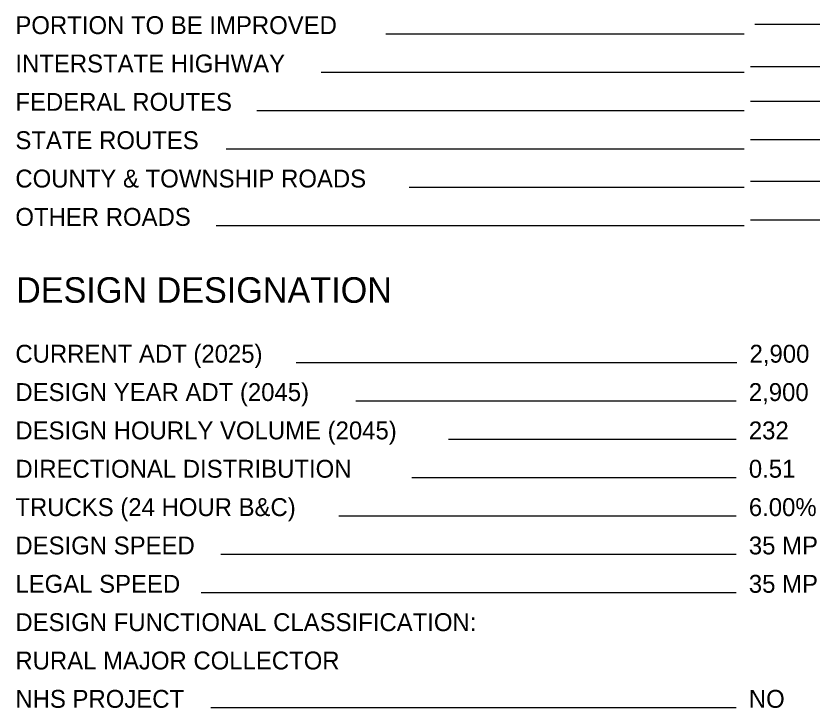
# Model space of a CAD drawing. Extents: x -13.9 to 69.1, y -25.2 to 26.1.
# Drawn here: x 1.73 to 7.96, y -18.58 to -13.17 of the extents above; entities that cross this region are included whole.
import ezdxf

# ---------------------------------------------------------------- set-up
doc = ezdxf.new("R2010")
doc.units = 0
doc.layers.add('SH_Data', color=7, linetype='Continuous')
doc.layers.add('SH_Text', color=7, linetype='Continuous')

msp = doc.modelspace()

# ---------------------------------------------------------------- linework, layer by layer
at = {"layer": 'SH_Data'}
for p, q in [((7.5134, -13.2313), (8.7308, -13.2313)), ((7.4308, -13.31), (4.6245, -13.31)), ((8.7308, -13.5659), (7.4808, -13.5659)), ((7.4308, -13.61), (4.1203, -13.61)), ((8.7308, -13.8376), (7.4808, -13.8376)), ((7.4308, -13.91), (3.6162, -13.91)), ((8.7308, -14.1376), (7.4808, -14.1376)), ((7.4308, -14.21), (3.3755, -14.21)), ((7.4308, -14.51), (4.8089, -14.51)), ((8.7308, -14.4643), (7.4808, -14.4643)), ((8.7308, -14.7643), (7.4808, -14.7643)), ((7.4308, -14.81), (3.2965, -14.81)), ((7.3732, -15.8804), (3.9244, -15.8804)), ((7.3676, -16.1804), (4.39, -16.1804)), ((7.3676, -16.4804), (5.116, -16.4804)), ((7.3676, -16.7804), (4.8295, -16.7804)), ((7.3676, -17.0804), (4.2566, -17.0804)), ((7.3676, -17.3804), (3.3343, -17.3804)), ((7.3676, -17.6804), (3.1796, -17.6804)), ((7.3676, -18.5804), (3.255, -18.5804))]:
    msp.add_line(p, q, dxfattribs=at)

# ---------------------------------------------------------------- texts
msp.add_text('DESIGN DESIGNATION', height=0.2, dxfattribs=at).set_placement((1.7308, -15.412))
at = {"layer": 'SH_Text'}
for s, p in [('PORTION TO BE IMPROVED', (1.7252, -13.31)), ('INTERSTATE HIGHWAY', (1.7252, -13.61)), ('FEDERAL ROUTES', (1.7252, -13.91)), ('STATE ROUTES', (1.7252, -14.21)), ('COUNTY & TOWNSHIP ROADS', (1.7252, -14.51)), ('OTHER ROADS', (1.7252, -14.81)), ('CURRENT ADT (2025)', (1.7252, -15.8804)), ('2,900', (7.4732, -15.8804)), ('DESIGN YEAR ADT (2045)', (1.7252, -16.1804)), ('2,900', (7.4676, -16.1804)), ('DESIGN HOURLY VOLUME (2045)', (1.7252, -16.4804)), ('232 ', (7.4676, -16.4804)), ('DIRECTIONAL DISTRIBUTION', (1.7252, -16.7804)), ('0.51', (7.4676, -16.7804)), ('TRUCKS (24 HOUR B&C)', (1.7252, -17.0804)), ('6.00%', (7.4676, -17.0804)), ('DESIGN SPEED', (1.7252, -17.3804)), ('35 MPH', (7.4676, -17.3804)), ('LEGAL SPEED', (1.7252, -17.6804)), ('35 MPH', (7.4676, -17.6804)), ('DESIGN FUNCTIONAL CLASSIFICATION:', (1.7252, -17.9804)), ('RURAL MAJOR COLLECTOR', (1.7252, -18.2804)), ('NHS PROJECT', (1.7252, -18.5804)), ('NO', (7.4676, -18.5804))]:
    msp.add_text(s, height=0.14, dxfattribs=at).set_placement(p)

doc.saveas('drawing.dxf')
